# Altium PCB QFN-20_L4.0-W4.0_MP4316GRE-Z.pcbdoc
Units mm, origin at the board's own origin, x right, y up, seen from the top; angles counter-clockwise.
Board outline 17.64 x 17.31 mm, 2 copper layers (Top Layer, Bottom Layer), stack 0 mm thick; 1 components, 0 nets, 23 pads, 0 vias.
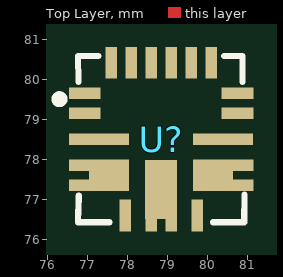
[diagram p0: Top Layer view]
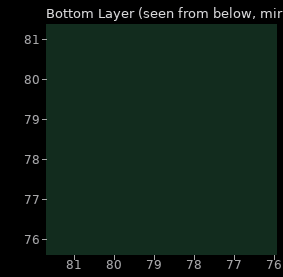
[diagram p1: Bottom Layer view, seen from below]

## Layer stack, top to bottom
Top Layer: signal copper (thickness not stored)
Bottom Layer: signal copper (thickness not stored)

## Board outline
87.493,69.85 69.85,69.85 69.85,87.155 87.493,87.155

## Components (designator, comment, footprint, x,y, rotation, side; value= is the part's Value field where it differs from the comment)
U? "" QFN-20_L4.0-W4.0_MP4316GRE-Z 78.841,78.503 r0 top

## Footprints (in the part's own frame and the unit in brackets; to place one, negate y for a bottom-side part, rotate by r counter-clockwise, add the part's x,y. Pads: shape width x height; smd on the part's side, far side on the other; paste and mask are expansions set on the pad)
QFN-20_L4.0-W4.0_MP4316GRE-Z [mm]
  rect 0.79x0.28 smd paste-100 mask+0.051: 1(-1.908,1.15) 2(-1.908,0.65) 4(-1.908,-0.65) 5(-1.908,-1.15) 10(1.908,-1.15) 11(1.908,-0.65) 13(1.908,0.65) 14(1.908,1.15)
  rect 1.5x0.28 smd paste-100 mask+0.051: 3(-1.55,0) 12(1.55,0)
  rect 1x0.78 smd paste-100 mask+0.051: 4(-1.3,-0.9) 10(1.3,-0.9)
  rect 0.28x0.79 smd paste-100 mask+0.051: 6(-0.9,-1.908) 7(-0.25,-1.908) 8(0.25,-1.908) 9(0.9,-1.908) 15(1.25,1.908) 16(0.75,1.908) 17(0.25,1.908) 18(-0.25,1.908) 19(-0.75,1.908) 20(-1.25,1.908)
  rect 0.8x1.475 smd paste-100 mask+0.05: 7(0,-1.263)
  silkscreen extent -2.64,-2.08 2.08,2.08

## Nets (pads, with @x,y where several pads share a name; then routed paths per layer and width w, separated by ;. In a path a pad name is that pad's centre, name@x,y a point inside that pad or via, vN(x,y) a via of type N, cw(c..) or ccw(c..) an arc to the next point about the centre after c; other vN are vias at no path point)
pads on no net: U?.1 U?.2 U?.3 U?.4 U?.5 U?.6 U?.7 U?.8 U?.9 U?.10 U?.11 U?.12 U?.13 U?.14 U?.15 U?.16 U?.17 U?.18 U?.19 U?.20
